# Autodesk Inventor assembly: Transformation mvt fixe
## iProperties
Author: Flavien MARTY
Shininess: 21.0
PropertySet Name: _Private Model Information
Created: 2001-10
Part Number: Transformation mvt fixe
Document SubType Name: Assemblage
Designer: Flavien MARTY
Control State: 0
Master: False
Checked Out: False
PropertySet Name: Design Tracking Control
Density: 0.0
Volumn: 0.0
Area: 0.0
PropertySet Name: Model Information
